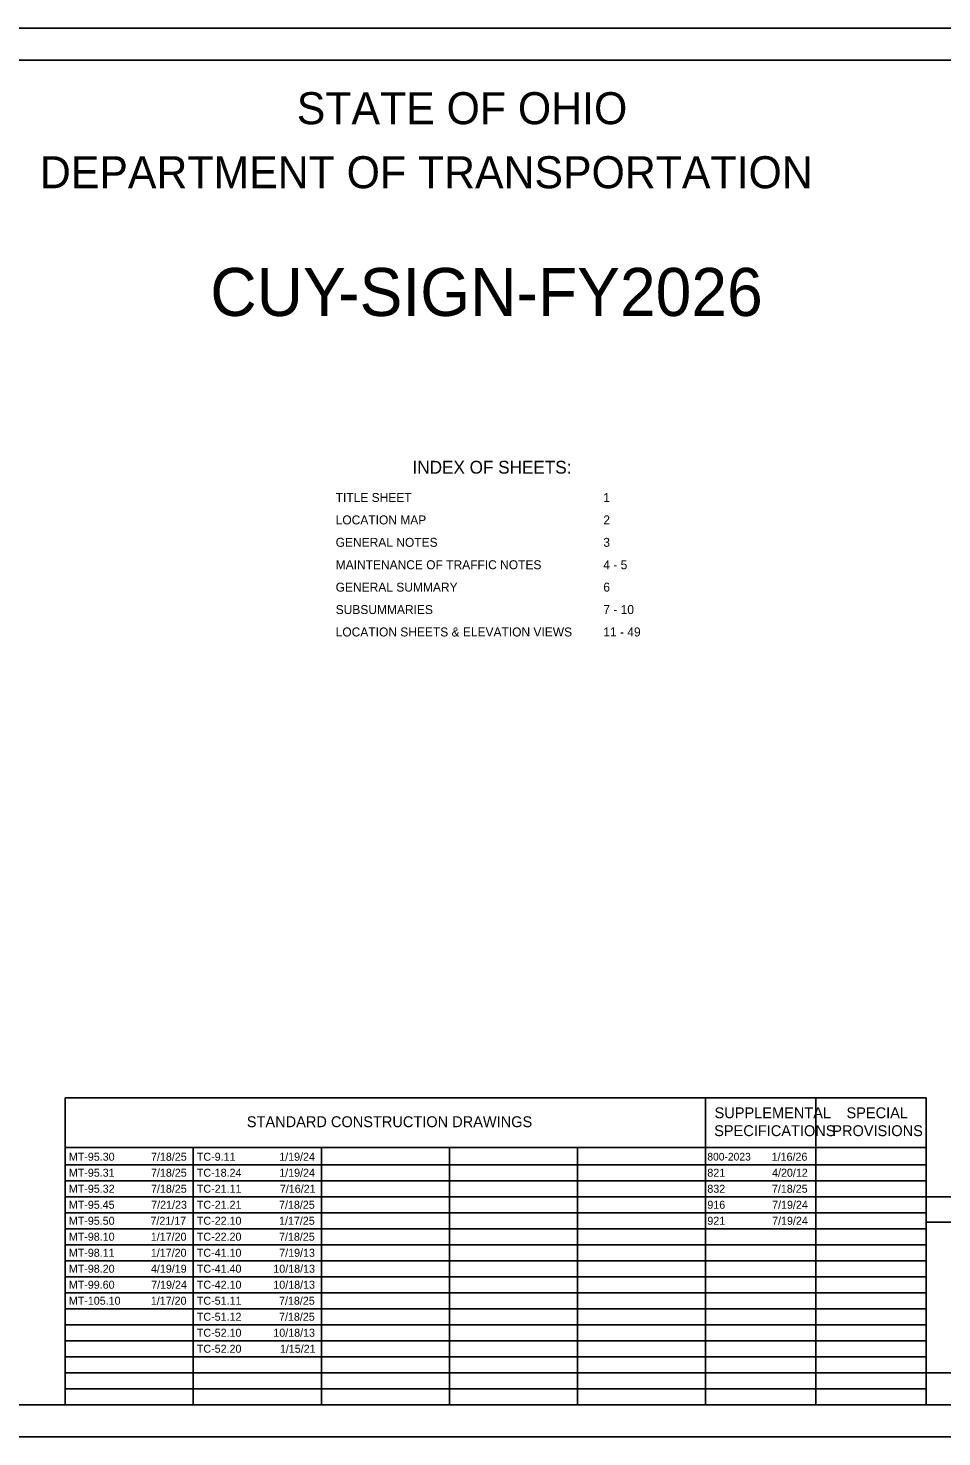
# Model space of a CAD drawing. Extents: x 0 to 42.4, y 0 to 22.
# Drawn here: x 9.57 to 23.84, y 0 to 22 of the extents above; entities that cross this region are included whole.
import ezdxf

# ---------------------------------------------------------------- set-up
doc = ezdxf.new("R2010")
doc.units = 0
for name, color, linetype in [('SH_Border', 7, 'Continuous'), ('SH_Cut_Line', 7, 'Continuous'), ('SH_Data', 7, 'Continuous'), ('SH_Text', 7, 'Continuous')]:
    doc.layers.add(name, color=color, linetype=linetype)

msp = doc.modelspace()

# ---------------------------------------------------------------- linework, layer by layer
at = {"layer": 'SH_Border'}
msp.add_lwpolyline([(1.5, 21.5), (33.5, 21.5), (33.5, 0.5), (1.5, 0.5)], close=True, dxfattribs=at)
at = {"layer": 'SH_Cut_Line'}
msp.add_lwpolyline([(0, 0), (34, 0), (34, 22), (0, 22)], close=True, dxfattribs=at)
at = {"layer": 'SH_Data'}
for p, q in [((10.15, 5.292), (23.6, 5.292)), ((10.15, 0.5), (10.15, 5.292)), ((20.15, 0.5), (20.15, 5.292)), ((21.875, 0.5), (21.875, 5.292)), ((23.6, 0.5), (23.6, 5.292)), ((10.15, 4.521), (23.6, 4.521)), ((12.15, 0.5), (12.15, 4.521)), ((14.15, 0.5), (14.15, 4.521)), ((16.15, 0.5), (16.15, 4.521)), ((18.15, 0.5), (18.15, 4.521)), ((10.15, 4.25), (23.6, 4.25)), ((10.15, 4), (23.6, 4)), ((10.15, 3.75), (23.6, 3.75)), ((23.6, 0.5), (23.6, 3.75)), ((23.6, 3.75), (26.4, 3.75)), ((10.15, 3.5), (23.6, 3.5)), ((23.6, 3.35), (26.4, 3.35)), ((10.15, 3.25), (23.6, 3.25)), ((10.15, 3), (23.6, 3)), ((10.15, 2.75), (23.6, 2.75)), ((10.15, 2.5), (23.6, 2.5)), ((10.15, 2.25), (23.6, 2.25)), ((10.15, 2), (23.6, 2)), ((10.15, 1.75), (23.6, 1.75)), ((10.15, 1.5), (23.6, 1.5)), ((10.15, 1.25), (23.6, 1.25)), ((10.15, 1), (23.6, 1)), ((10.15, 0.75), (23.6, 0.75)), ((23.6, 0.5), (26.4, 0.5))]:
    msp.add_line(p, q, dxfattribs=at)
msp.add_lwpolyline([(23.6, 0.5), (23.6, 1), (26.4, 1), (26.4, 0.5)], close=True, dxfattribs=at)

# ---------------------------------------------------------------- texts
at = {"layer": 'SH_Text'}
for s, height, p in [('STATE OF OHIO', 0.5, (13.766, 20.5)), ('DEPARTMENT OF TRANSPORTATION', 0.5, (9.753, 19.5)), ('CUY', 0.75, (12.415, 17.505)), ('-SIGN-FY2026', 0.75, (14.413, 17.505)), ('INDEX OF SHEETS:', 0.2, (15.575, 15.043)), ('TITLE SHEET', 0.14, (14.374, 14.6)), ('1 ', 0.14, (18.555, 14.6)), ('LOCATION MAP', 0.14, (14.374, 14.25)), ('2 ', 0.14, (18.555, 14.25)), ('GENERAL NOTES', 0.14, (14.374, 13.9)), ('3', 0.14, (18.555, 13.9)), ('MAINTENANCE OF TRAFFIC NOTES', 0.14, (14.374, 13.55)), ('4 - 5', 0.14, (18.555, 13.55)), ('GENERAL SUMMARY', 0.14, (14.374, 13.2)), ('6', 0.14, (18.555, 13.2)), ('SUBSUMMARIES', 0.14, (14.374, 12.85)), ('7 - 10', 0.14, (18.555, 12.85)), ('LOCATION SHEETS & ELEVATION VIEWS', 0.14, (14.374, 12.5)), ('11 - 49', 0.14, (18.555, 12.5)), ('SUPPLEMENTAL', 0.17, (20.293, 4.976)), ('SPECIAL', 0.17, (22.354, 4.976)), ('STANDARD CONSTRUCTION DRAWINGS', 0.17, (12.986, 4.836)), ('SPECIFICATIONS', 0.17, (20.287, 4.696)), ('PROVISIONS', 0.17, (22.132, 4.696)), ('MT-95.30', 0.125, (10.205, 4.312)), ('7/18/25', 0.125, (11.489, 4.312)), ('TC-9.11', 0.125, (12.205, 4.312)), ('1/19/24', 0.125, (13.492, 4.312)), ('800-2023', 0.12, (20.18, 4.315)), ('1/16/26', 0.125, (21.185, 4.312)), ('MT-95.31', 0.125, (10.205, 4.062)), ('7/18/25', 0.125, (11.489, 4.062)), ('TC-18.24', 0.125, (12.205, 4.062)), ('1/19/24', 0.125, (13.492, 4.062)), ('821', 0.125, (20.18, 4.062)), ('4/20/12', 0.125, (21.191, 4.062)), ('MT-95.32', 0.125, (10.205, 3.812)), ('7/18/25', 0.125, (11.489, 3.812)), ('TC-21.11', 0.125, (12.205, 3.812)), ('7/16/21', 0.125, (13.502, 3.812)), ('832', 0.125, (20.18, 3.812)), ('7/18/25', 0.125, (21.189, 3.812)), ('MT-95.45', 0.125, (10.205, 3.562)), ('7/21/23', 0.125, (11.492, 3.562)), ('TC-21.21', 0.125, (12.205, 3.562)), ('7/18/25', 0.125, (13.489, 3.562)), ('916', 0.125, (20.18, 3.562)), ('7/19/24', 0.125, (21.192, 3.562)), ('MT-95.50', 0.125, (10.205, 3.312)), ('7/21/17', 0.125, (11.48, 3.312)), ('TC-22.10', 0.125, (12.205, 3.312)), ('1/17/25', 0.125, (13.489, 3.312)), ('921', 0.125, (20.18, 3.312)), ('7/19/24', 0.125, (21.192, 3.312)), ('MT-98.10', 0.125, (10.205, 3.063)), ('1/17/20', 0.125, (11.486, 3.063)), ('TC-22.20', 0.125, (12.205, 3.063)), ('7/18/25', 0.125, (13.489, 3.063)), ('MT-98.11', 0.125, (10.205, 2.812)), ('1/17/20', 0.125, (11.486, 2.812)), ('TC-41.10', 0.125, (12.205, 2.812)), ('7/19/13', 0.125, (13.492, 2.812)), ('MT-98.20', 0.125, (10.205, 2.563)), ('4/19/19', 0.125, (11.488, 2.563)), ('TC-41.40', 0.125, (12.205, 2.563)), ('10/18/13', 0.125, (13.4, 2.563)), ('MT-99.60', 0.125, (10.205, 2.313)), ('7/19/24', 0.125, (11.492, 2.313)), ('TC-42.10', 0.125, (12.205, 2.313)), ('10/18/13', 0.125, (13.4, 2.313)), ('MT-105.10', 0.125, (10.205, 2.063)), ('1/17/20', 0.125, (11.486, 2.063)), ('TC-51.11', 0.125, (12.205, 2.063)), ('7/18/25', 0.125, (13.489, 2.063)), ('TC-51.12', 0.125, (12.205, 1.813)), ('7/18/25', 0.125, (13.489, 1.813)), ('TC-52.10', 0.125, (12.205, 1.563)), ('10/18/13', 0.125, (13.4, 1.563)), ('TC-52.20', 0.125, (12.205, 1.313)), ('1/15/21', 0.125, (13.502, 1.313))]:
    msp.add_text(s, height=height, dxfattribs=at).set_placement(p)

doc.saveas('drawing.dxf')
